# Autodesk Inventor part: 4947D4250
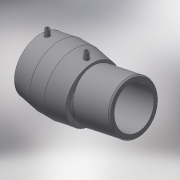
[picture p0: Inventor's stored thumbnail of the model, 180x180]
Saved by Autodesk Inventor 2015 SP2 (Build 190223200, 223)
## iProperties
Created: 2017-06
Part Number: 4947D4250
Material: Generic
Description: PLASSON ADJUSTABLE ELBOW (ONE SIDE) 250
Document SubType Name: Modeling
Designer: KIM
Mass: 55.0731 g
Surface Area: 148.067 cm^2
Volume: 55.0731 cm^3
Density: 1 g/cm^3
Appearance: Default
Author: KIM
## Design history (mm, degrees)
derived "4947D4.ipt"
feature "Solid1::4947D4.ipt"
tag "TaggingFeature1"
body "Solid1"
other parameters: "d0" = 238.875, "d2" = 312, "d3" = 123, "d4" = 61.5, "d5" = 280.8, "d8" = 168 deg, "d10" = 49.2, "d11" = 16.4, "d29" = 156, "d30" = 15, "d31" = 91, "d34" = 5 deg, "d41" = 4, "d42" = 14, "d43" = 0, "d48" = 225, "d55" = 69.525, "d57" = 168 deg, "d62" = 3, "d63" = 0, "d65" = 455, "d67" = 225, "d68" = 135 deg, "d69" = 134, "d70" = 115.44, "d71" = 6.24, "L_" = 455, "L_1" = 123, "D_" = 312, "A_" = 156, "d_2" = 12, "L_0" = 148, "L_2" = 134, "d54" = 115.875, "d59" = 285.77957
